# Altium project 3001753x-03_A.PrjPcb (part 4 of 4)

## Sheet 19 - System power rails, GPIO table.SchDoc: System power rails, GPIO table
size A3; PageSetup: Record=PageOptions¦CenterHorizontal=True¦CenterVertical=True¦PrintScale=1.01¦XCorrection=1.00¦YCorrection=1.00¦PrintKind=0¦BorderSize=5000000¦LeftOffset=0¦BottomOffset=0¦Orientation=2¦PaperLength=4200¦PaperWidth=2970¦Scale=100¦PaperSource=15¦PrintQuality=600¦MediaType=1¦DitherType=10¦PrintScaleMode=1¦PaperKind=A3¦PaperIndex=8; Author: Juan Anzola; SheetNumber: 19; SheetTotal: 20
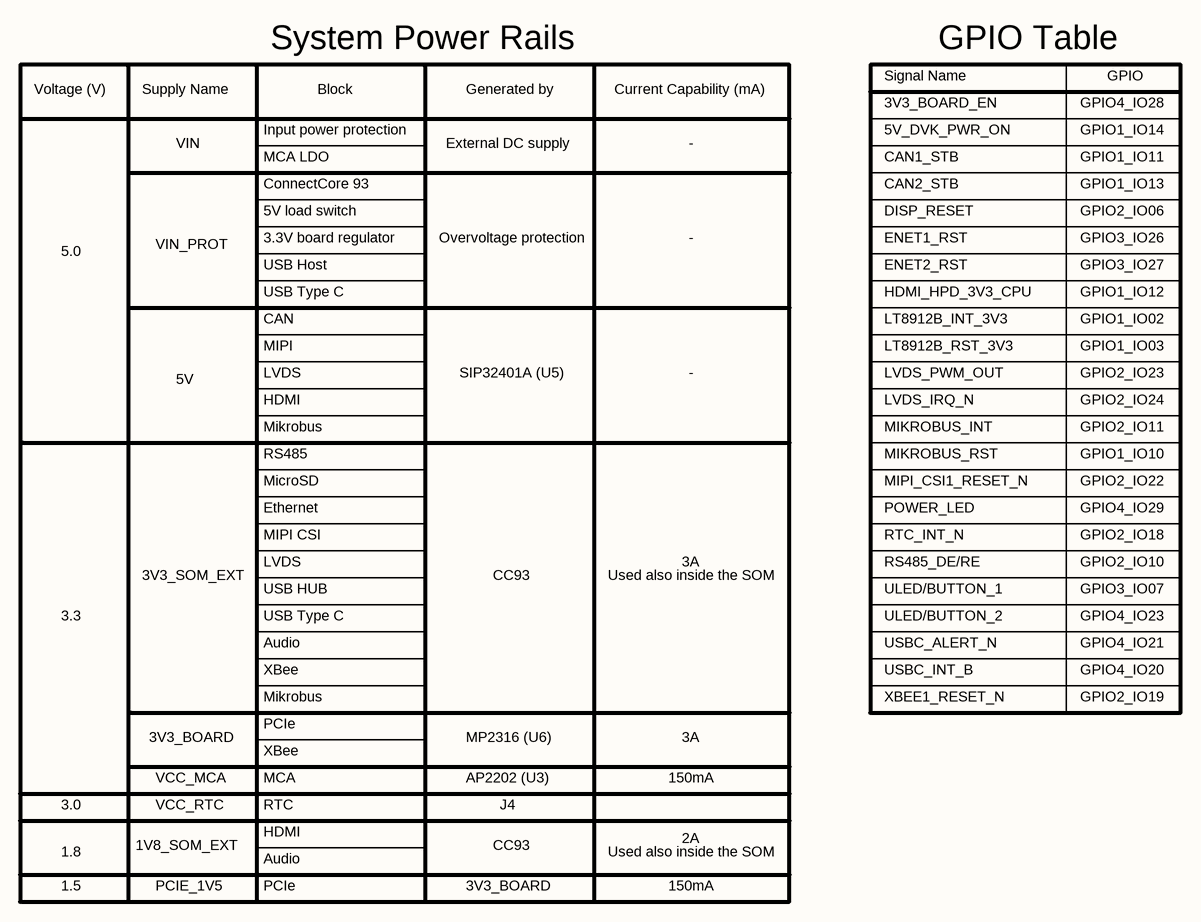
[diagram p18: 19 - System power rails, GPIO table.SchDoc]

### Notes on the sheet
- Voltage (V)
- Supply Name
- System Power Rails
- Block
- Generated by
- Current Capability (mA)
- Signal Name
- GPIO Table
- GPIO
- VIN
- Input power protection
- External DC supply
- -
- 3V3_BOARD_EN
- 5V_DVK_PWR_ON
- GPIO1_IO14
- GPIO4_IO28
- MCA LDO
- ConnectCore 93
- 5V load switch
- CAN1_STB
- CAN2_STB
- DISP_RESET
- GPIO1_IO13
- GPIO1_IO11
- GPIO2_IO06
- 5.0
- VIN_PROT
- USB Host
- 3.3V board regulator
- Overvoltage protection
- ENET1_RST
- ENET2_RST
- GPIO3_IO26
- GPIO3_IO27
- USB Type C
- CAN
- MIPI
- LT8912B_INT_3V3
- HDMI_HPD_3V3_CPU
- LT8912B_RST_3V3
- GPIO1_IO02
- GPIO1_IO03
- GPIO1_IO12
- 5V
- HDMI
- LVDS
- SIP32401A (U5)
- LVDS_PWM_OUT
- LVDS_IRQ_N
- GPIO2_IO24
- GPIO2_IO23
- MicroSD
- Mikrobus
- RS485
- MIPI_CSI1_RESET_N
- MIKROBUS_INT
- MIKROBUS_RST
- GPIO2_IO22
- GPIO2_IO11
- GPIO1_IO10
- Ethernet
- MIPI CSI
- POWER_LED
- RTC_INT_N
- GPIO4_IO29
- GPIO2_IO18
- 3.3
- 3V3_SOM_EXT
- USB HUB
- CC93
- Used also inside the SOM
- 3A
- ULED/BUTTON_1
- RS485_DE/RE
- ULED/BUTTON_2
- GPIO2_IO10
- GPIO3_IO07
- GPIO4_IO23
- Audio
- XBee
- USBC_ALERT_N
- USBC_INT_B
- GPIO4_IO21
- GPIO4_IO20
- 3V3_BOARD
- PCIe
- MP2316 (U6)
- XBEE1_RESET_N
- GPIO2_IO19
- 3.0
- VCC_MCA
- VCC_RTC
- MCA
- RTC
- AP2202 (U3)
- J4
- 150mA
- 1.8
- 1.5
- 1V8_SOM_EXT
- PCIE_1V5
- 2A

## Sheet 20 - History, Mechanicals.SchDoc: History, Mechanicals
size A3; PageSetup: Record=PageOptions¦CenterHorizontal=True¦CenterVertical=True¦PrintScale=1.01¦XCorrection=1.00¦YCorrection=1.00¦PrintKind=0¦BorderSize=5000000¦LeftOffset=0¦BottomOffset=0¦Orientation=2¦PaperLength=4200¦PaperWidth=2970¦Scale=100¦PaperSource=15¦PrintQuality=600¦MediaType=1¦DitherType=10¦PrintScaleMode=1¦PaperKind=A3¦PaperIndex=8; Author: Juan Anzola; SheetNumber: 20; SheetTotal: 20
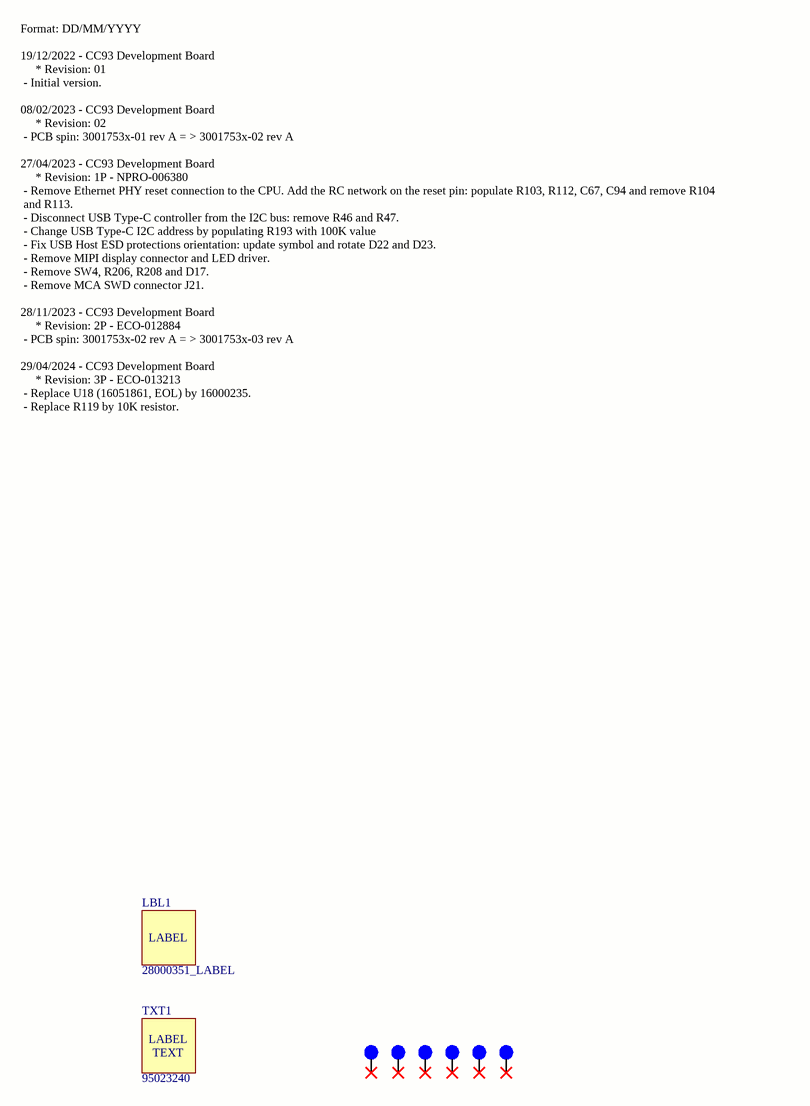
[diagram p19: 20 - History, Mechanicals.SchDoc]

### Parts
FIDUCIAL1  40mil FID  [fiducial_40mil_round]  (value not drawn)  (no BOM)
FIDUCIAL2  40mil FID  [fiducial_40mil_round]  (value not drawn)  (no BOM)
FIDUCIAL3  40mil FID  [fiducial_40mil_round]  (value not drawn)  (no BOM)
FIDUCIAL4  40mil FID  [fiducial_40mil_round]  (value not drawn)  (no BOM)
FIDUCIAL5  40mil FID  [fiducial_40mil_round]  (value not drawn)  (no BOM)
FIDUCIAL6  40mil FID  [fiducial_40mil_round]  (value not drawn)  (no BOM)
LBL1  28000351_LABEL
TXT1  95023240  (mechanical)

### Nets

Not connected (* = marked no-connect by the designer): FIDUCIAL1 1(Fid_1)*; FIDUCIAL2 1(Fid_1)*; FIDUCIAL3 1(Fid_1)*; FIDUCIAL4 1(Fid_1)*; FIDUCIAL5 1(Fid_1)*; FIDUCIAL6 1(Fid_1)*

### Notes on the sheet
- Format: DD/MM/YYYY
  19/12/2022 - CC93 Development Board
  * Revision: 01
  - Initial version.
  08/02/2023 - CC93 Development Board
  * Revision: 02
  - PCB spin: 3001753x-01 rev A = > 3001753x-02 rev A
  27/04/2023 - CC93 Development Board
  * Revision: 1P - NPRO-006380
  - Remove Ethernet PHY reset connection to the CPU. Add the RC network on the reset pin: populate R103, R112, C67, C94 and remove R104
  and R113.
  - Disconnect USB Type-C controller from the I2C bus: remove R46 and R47.
  - Change USB Type-C I2C address by populating R193 with 100K value
  - Fix USB Host ESD protections orientation: update symbol and rotate D22 and D23.
  - Remove MIPI display connector and LED driver.
  - Remove SW4, R206, R208 and D17.
  - Remove MCA SWD connector J21.
  28/11/2023 - CC93 Development Board
  * Revision: 2P - ECO-012884
  - PCB spin: 3001753x-02 rev A = > 3001753x-03 rev A
  29/04/2024 - CC93 Development Board
  * Revision: 3P - ECO-013213
  - Replace U18 (16051861, EOL) by 16000235.
  - Replace R119 by 10K resistor.

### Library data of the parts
FIDUCIAL1-FIDUCIAL6 = CAD0023: 40 Mil Round Fiducial; Part_Type: Mechanical; Component_Life_Cycle_State: Reviewed; Area: 1; Project: SDR Prototype RF Board
LBL1 = 1002170: LBL,Poly White Blank 0.40x0.40; Manufacturer: 3M; Manufacturer_Part_Number: TAAE-014000; Noplace: False; Component_Life_Cycle_State: Created; Area: 100; Project: CCWMX6_SBC board
TXT1 = CAD0111: LBL,.5x.75" 55002179-01 CC93 DVK; Part_Type: Label; Noplace: False; Component_Life_Cycle_State: Pending

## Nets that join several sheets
1V8: 03 - CCIMX93 Power, Control, MCA (6 pins), 18 - Expansion connectors, LEDs and buttons (J47.5 J65.1 R203.1)
1V8_SOM_EXT: 03 - CCIMX93 Power, Control, MCA (J8.1 R44.2), 06 - Shared interfaces lines selection (9 pins), 08 - JTAG, SWD, uSD, Mini PCIe, uSIM (J20.1), 09 - Gigabit Ethernet 1 (R238.1), 10 - Gigabit Ethernet 2 (R239.1), 12 - MIPI to HDMI bridge (35 pins), 16 - Audio (R171.1), 17 - I2C, XBee, MIKROBUS (R172.2 R174.2 U28.2 U28.5)
3V3: 03 - CCIMX93 Power, Control, MCA (8 pins), 07 - Console, CAN, RS485, RTC (J18.3 R73.1), 15 - Bootstrap (C157.2 R151.2 U26.20), 18 - Expansion connectors, LEDs and buttons (J47.3 J65.2)
3V3_BOARD: 02 - Power, reset (7 pins), 08 - JTAG, SWD, uSD, Mini PCIe, uSIM (17 pins), 17 - I2C, XBee, MIKROBUS (L39.1), 18 - Expansion connectors, LEDs and buttons (R15.2)
3V3_RF: 03 - CCIMX93 Power, Control, MCA (U7.F17 U7.F18), 05 - CCIMX93 RF (J12.2), 18 - Expansion connectors, LEDs and buttons (J41.1)
3V3_SOM_EXT: 02 - Power, reset (D35.A R29.2), 03 - CCIMX93 Power, Control, MCA (J7.1 R43.2), 06 - Shared interfaces lines selection (6 pins), 07 - Console, CAN, RS485, RTC (9 pins), 08 - JTAG, SWD, uSD, Mini PCIe, uSIM (R87.2 R88.2), 09 - Gigabit Ethernet 1 (R105.1), 10 - Gigabit Ethernet 2 (J34.1 R205.1), 11 - MIPI switch and display, MIPI camera, LVDS (15 pins), 12 - MIPI to HDMI bridge (D15.A R131.2 R134.2 R137.2), 13 - USB HUB (R141.1), 14 - USB Type C (5 pins), 15 - Bootstrap (R153.2 R155.2 R156.2), 16 - Audio (R160.1 R170.1), 17 - I2C, XBee, MIKROBUS (8 pins), 18 - Expansion connectors, LEDs and buttons (R12.2 R206.2 R207.2)
5V: 02 - Power, reset (R24.2), 07 - Console, CAN, RS485, RTC (6 pins), 11 - MIPI switch and display, MIPI camera, LVDS (L17.1 R216.1), 12 - MIPI to HDMI bridge (C111.2 C112.2 U18.1), 17 - I2C, XBee, MIKROBUS (C146.1 J40.7), 18 - Expansion connectors, LEDs and buttons (R195.2)
GND: 02 - Power, reset (49 pins), 03 - CCIMX93 Power, Control, MCA (166 pins), 05 - CCIMX93 RF (11 pins), 06 - Shared interfaces lines selection (9 pins), 07 - Console, CAN, RS485, RTC (49 pins), 08 - JTAG, SWD, uSD, Mini PCIe, uSIM (69 pins), 09 - Gigabit Ethernet 1 (36 pins), 10 - Gigabit Ethernet 2 (35 pins), 11 - MIPI switch and display, MIPI camera, LVDS (46 pins), 12 - MIPI to HDMI bridge (56 pins), 13 - USB HUB (36 pins), 14 - USB Type C (23 pins), 15 - Bootstrap (8 pins), 16 - Audio (29 pins), 17 - I2C, XBee, MIKROBUS (10 pins), 18 - Expansion connectors, LEDs and buttons (17 pins)
LDO2: 03 - CCIMX93 Power, Control, MCA (R36.1), 18 - Expansion connectors, LEDs and buttons (J47.1)
LDO3: 03 - CCIMX93 Power, Control, MCA (R37.1), 08 - JTAG, SWD, uSD, Mini PCIe, uSIM (R243.1), 18 - Expansion connectors, LEDs and buttons (J47.2)
MUX_3V3_1V8: 03 - CCIMX93 Power, Control, MCA (R38.1 R39.1), 08 - JTAG, SWD, uSD, Mini PCIe, uSIM (R84.2 R85.2)
SHLD: 09 - Gigabit Ethernet 1 (J26.SHLD1 J26.SHLD2 R100.2), 10 - Gigabit Ethernet 2 (J27.SHLD1 J27.SHLD2), 12 - MIPI to HDMI bridge (J32.M1 J32.M2 J32.M3 J32.M4), 13 - USB HUB (J33.SH1 J33.SH2 J33.SH3 J33.SH4), 14 - USB Type C (J63.MT1 J63.MT2 J63.MT3 J63.MT4)
SUPERCAP: 02 - Power, reset (C9.1 J5.2 R242.1), 07 - Console, CAN, RS485, RTC (R227.2)
SWIN: 03 - CCIMX93 Power, Control, MCA (R41.1), 18 - Expansion connectors, LEDs and buttons (J47.7)
SWOUT: 03 - CCIMX93 Power, Control, MCA (R42.1), 18 - Expansion connectors, LEDs and buttons (J47.8)
VCC_MCA: 02 - Power, reset (7 pins), 03 - CCIMX93 Power, Control, MCA (J9.1 U7.AM21), 08 - JTAG, SWD, uSD, Mini PCIe, uSIM (J21.1 SWD.1 SWD.5), 18 - Expansion connectors, LEDs and buttons (J42.1 J42.2 J47.6)
VCC_RTC: 02 - Power, reset (D2.2 R17.2), 07 - Console, CAN, RS485, RTC (R226.2)
VIN_PROT: 02 - Power, reset (15 pins), 03 - CCIMX93 Power, Control, MCA (J6.1 R33.1), 04 - CCIMX93 Digital interfaces (U7.B6 U7.E7), 13 - USB HUB (C139.1 U19.7), 14 - USB Type C (6 pins), 17 - I2C, XBee, MIKROBUS (R196.1), 18 - Expansion connectors, LEDs and buttons (R154.2)
3V3_BOARD_EN: 02 - Power, reset (Q11.G), 04 - CCIMX93 Digital interfaces (U7.AG25)
5V_DVK_PWR_ON: 02 - Power, reset (R29.1 U5.4), 04 - CCIMX93 Digital interfaces (U7.D18)
15.4_SPI_CLK: 05 - CCIMX93 RF (U7.F8), 18 - Expansion connectors, LEDs and buttons (J44.10)
15.4_SPI_FRM: 05 - CCIMX93 RF (U7.F4), 18 - Expansion connectors, LEDs and buttons (J44.2)
15.4_SPI_INT: 05 - CCIMX93 RF (U7.F5), 18 - Expansion connectors, LEDs and buttons (J44.4)
15.4_SPI_RXD: 05 - CCIMX93 RF (U7.F6), 18 - Expansion connectors, LEDs and buttons (J44.6)
15.4_SPI_TXD: 05 - CCIMX93 RF (U7.F7), 18 - Expansion connectors, LEDs and buttons (J44.8)
ADC_IN0: 04 - CCIMX93 Digital interfaces (U7.K29), 18 - Expansion connectors, LEDs and buttons (J48.1)
ADC_IN1: 04 - CCIMX93 Digital interfaces (U7.L29), 18 - Expansion connectors, LEDs and buttons (J48.3)
ADC_IN2: 04 - CCIMX93 Digital interfaces (U7.AG27), 18 - Expansion connectors, LEDs and buttons (J48.5)
ADC_IN3: 04 - CCIMX93 Digital interfaces (U7.AG26), 18 - Expansion connectors, LEDs and buttons (J48.7)
AUD_I2C_SCL: 16 - Audio (U27.51), 17 - I2C, XBee, MIKROBUS (R179.2)
AUD_I2C_SDA: 16 - Audio (U27.52), 17 - I2C, XBee, MIKROBUS (R183.2)
BT_DEV_WAKE: 05 - CCIMX93 RF (U7.G12), 18 - Expansion connectors, LEDs and buttons (J41.15)
BT_HOST_WAKE: 05 - CCIMX93 RF (U7.G17), 18 - Expansion connectors, LEDs and buttons (J41.13)
BT_UART1_CTS: 05 - CCIMX93 RF (R63.2), 18 - Expansion connectors, LEDs and buttons (J41.7)
BT_UART1_RTS: 05 - CCIMX93 RF (R64.2), 15 - Bootstrap (SW3.2 U26.3)
BT_UART1_RTS_PROT: 15 - Bootstrap (U26.17), 18 - Expansion connectors, LEDs and buttons (J41.9)
BT_UART1_RX: 05 - CCIMX93 RF (R62.2), 18 - Expansion connectors, LEDs and buttons (J41.5)
BT_UART1_TX: 05 - CCIMX93 RF (R61.2), 15 - Bootstrap (R159.2 SW3.1 U26.2)
BT_UART1_TX_PROT: 15 - Bootstrap (U26.18), 18 - Expansion connectors, LEDs and buttons (J41.3)
CAN1_RX: 04 - CCIMX93 Digital interfaces (U7.U29), 07 - Console, CAN, RS485, RTC (U8.4)
CAN1_STB: 04 - CCIMX93 Digital interfaces (U7.C17), 15 - Bootstrap (R158.2 SW3.3 U26.4)
CAN1_STB_PROT: 07 - Console, CAN, RS485, RTC (R67.2 U8.8), 15 - Bootstrap (U26.16)
CAN1_TX: 04 - CCIMX93 Digital interfaces (U7.T29), 07 - Console, CAN, RS485, RTC (U8.1)
CAN2_RX: 04 - CCIMX93 Digital interfaces (U7.R29), 07 - Console, CAN, RS485, RTC (U10.4)
CAN2_STB: 04 - CCIMX93 Digital interfaces (U7.E17), 15 - Bootstrap (R157.2 SW3.4 U26.5)
CAN2_STB_PROT: 07 - Console, CAN, RS485, RTC (R78.2 U10.8), 15 - Bootstrap (U26.15)
CAN2_TX: 04 - CCIMX93 Digital interfaces (U7.P29), 07 - Console, CAN, RS485, RTC (U10.1)
CLKIN1: 03 - CCIMX93 Power, Control, MCA (U7.AM10), 18 - Expansion connectors, LEDs and buttons (J48.2)
CLKIN2: 03 - CCIMX93 Power, Control, MCA (U7.AM11), 18 - Expansion connectors, LEDs and buttons (J48.4)
CONSOLE_RX: 04 - CCIMX93 Digital interfaces (U7.V29), 07 - Console, CAN, RS485, RTC (D9.2 J18.2 R68.1)
CONSOLE_TX: 04 - CCIMX93 Digital interfaces (U7.W29), 07 - Console, CAN, RS485, RTC (D10.2 J18.1 R69.1)
DISP_RESET: 04 - CCIMX93 Digital interfaces (U7.AA1), 11 - MIPI switch and display, MIPI camera, LVDS (J29.7 R214.2 R218.1)
ENET1_MDC: 04 - CCIMX93 Digital interfaces (U7.A10), 09 - Gigabit Ethernet 1 (U13.7)
ENET1_MDIO: 04 - CCIMX93 Digital interfaces (U7.A11), 09 - Gigabit Ethernet 1 (R99.2 U13.8)
ENET1_RD0: 04 - CCIMX93 Digital interfaces (U7.A16), 09 - Gigabit Ethernet 1 (U13.44)
ENET1_RD1: 04 - CCIMX93 Digital interfaces (U7.A15), 09 - Gigabit Ethernet 1 (U13.45)
ENET1_RD2: 04 - CCIMX93 Digital interfaces (U7.A14), 09 - Gigabit Ethernet 1 (U13.47)
ENET1_RD3: 04 - CCIMX93 Digital interfaces (U7.A13), 09 - Gigabit Ethernet 1 (U13.48)
ENET1_RX_CTL: 04 - CCIMX93 Digital interfaces (U7.A17), 09 - Gigabit Ethernet 1 (U13.43)
ENET1_RXC: 04 - CCIMX93 Digital interfaces (U7.A18), 09 - Gigabit Ethernet 1 (U13.46)
ENET1_TD0: 04 - CCIMX93 Digital interfaces (U7.A22), 09 - Gigabit Ethernet 1 (U13.50)
ENET1_TD1: 04 - CCIMX93 Digital interfaces (U7.A21), 09 - Gigabit Ethernet 1 (U13.51)
ENET1_TD2: 04 - CCIMX93 Digital interfaces (U7.A20), 09 - Gigabit Ethernet 1 (U13.54)
ENET1_TD3: 04 - CCIMX93 Digital interfaces (U7.A19), 09 - Gigabit Ethernet 1 (U13.55)
ENET1_TX_CTL: 04 - CCIMX93 Digital interfaces (U7.A23), 09 - Gigabit Ethernet 1 (U13.56)
ENET1_TXC: 04 - CCIMX93 Digital interfaces (U7.A24), 09 - Gigabit Ethernet 1 (U13.53)
ENET2_MDC: 04 - CCIMX93 Digital interfaces (U7.AF1), 10 - Gigabit Ethernet 2 (U14.7)
ENET2_MDIO: 04 - CCIMX93 Digital interfaces (U7.AG1), 10 - Gigabit Ethernet 2 (R109.2 U14.8)
ENET2_RD0: 06 - Shared interfaces lines selection (J54.1), 10 - Gigabit Ethernet 2 (U14.44)
ENET2_RD0/UART4_RX: 04 - CCIMX93 Digital interfaces (U7.D21), 06 - Shared interfaces lines selection (J54.2)
ENET2_RD1: 06 - Shared interfaces lines selection (J56.1), 10 - Gigabit Ethernet 2 (U14.45)
ENET2_RD1/GPIO4_IO25: 04 - CCIMX93 Digital interfaces (U7.D23), 06 - Shared interfaces lines selection (J56.2)
ENET2_RD2: 06 - Shared interfaces lines selection (J58.1), 10 - Gigabit Ethernet 2 (U14.47)
ENET2_RD2/UART4_CTS: 04 - CCIMX93 Digital interfaces (U7.C20), 06 - Shared interfaces lines selection (J58.2)
ENET2_RD3: 06 - Shared interfaces lines selection (J60.1), 10 - Gigabit Ethernet 2 (U14.48)
ENET2_RD3/GPIO4_IO27: 04 - CCIMX93 Digital interfaces (U7.B22), 06 - Shared interfaces lines selection (J60.2)
ENET2_RX_CTL: 06 - Shared interfaces lines selection (J55.1), 10 - Gigabit Ethernet 2 (U14.43)
ENET2_RX_CTL/GPIO4_IO22: 04 - CCIMX93 Digital interfaces (U7.C23), 06 - Shared interfaces lines selection (J55.2)
ENET2_RXC: 06 - Shared interfaces lines selection (J53.1), 10 - Gigabit Ethernet 2 (U14.46)
ENET2_RXC/GPIO4_IO23: 04 - CCIMX93 Digital interfaces (U7.D22), 06 - Shared interfaces lines selection (J53.2)
ENET2_TD0: 06 - Shared interfaces lines selection (J57.1), 10 - Gigabit Ethernet 2 (U14.50)
ENET2_TD0/UART4_TX: 04 - CCIMX93 Digital interfaces (U7.C22), 06 - Shared interfaces lines selection (J57.2)
ENET2_TD1: 06 - Shared interfaces lines selection (J59.1), 10 - Gigabit Ethernet 2 (U14.51)
ENET2_TD1/UART4_RTS: 04 - CCIMX93 Digital interfaces (U7.D20), 06 - Shared interfaces lines selection (J59.2)
ENET2_TD2: 06 - Shared interfaces lines selection (J45.1), 10 - Gigabit Ethernet 2 (U14.54)
ENET2_TD2/GPIO4_IO17: 04 - CCIMX93 Digital interfaces (U7.C21), 06 - Shared interfaces lines selection (J45.2)
ENET2_TD3: 06 - Shared interfaces lines selection (J52.1), 10 - Gigabit Ethernet 2 (U14.55)
ENET2_TD3/GPIO4_IO16: 04 - CCIMX93 Digital interfaces (U7.B21), 06 - Shared interfaces lines selection (J52.2)
ENET2_TX_CTL: 06 - Shared interfaces lines selection (J51.1), 10 - Gigabit Ethernet 2 (U14.56)
ENET2_TX_CTL/GPIO4_IO20: 04 - CCIMX93 Digital interfaces (U7.B19), 06 - Shared interfaces lines selection (J51.2)
ENET2_TXC: 06 - Shared interfaces lines selection (J43.1), 10 - Gigabit Ethernet 2 (U14.53)
ENET2_TXC/GPIO4_IO21: 04 - CCIMX93 Digital interfaces (U7.B20), 06 - Shared interfaces lines selection (J43.2)
GPIO3_IO26_1V8: 04 - CCIMX93 Digital interfaces (U7.AL18), 12 - MIPI to HDMI bridge (R244.2), 18 - Expansion connectors, LEDs and buttons (J65.3)
GPIO3_IO27_1V8: 04 - CCIMX93 Digital interfaces (U7.D25), 18 - Expansion connectors, LEDs and buttons (J65.5)
GPIO4_IO16_1V8: 06 - Shared interfaces lines selection (J52.3), 18 - Expansion connectors, LEDs and buttons (J65.7)
GPIO4_IO17_1V8: 06 - Shared interfaces lines selection (J45.3), 18 - Expansion connectors, LEDs and buttons (J65.9)
GPIO4_IO22_1V8: 06 - Shared interfaces lines selection (J55.3), 18 - Expansion connectors, LEDs and buttons (J65.4)
GPIO4_IO25_1V8: 06 - Shared interfaces lines selection (J56.3), 18 - Expansion connectors, LEDs and buttons (J65.6)
GPIO4_IO27_1V8: 06 - Shared interfaces lines selection (J60.3), 18 - Expansion connectors, LEDs and buttons (J65.8)
HDMI_HPD_3V3_CPU: 04 - CCIMX93 Digital interfaces (U7.C18), 12 - MIPI to HDMI bridge (Q3.D R131.1 R132.2)
HDMI_SCL_1V8: 12 - MIPI to HDMI bridge (U18.17), 17 - I2C, XBee, MIKROBUS (R185.2)
HDMI_SDA_1V8: 12 - MIPI to HDMI bridge (U18.18), 17 - I2C, XBee, MIKROBUS (R187.2)
I2C3_SCL: 04 - CCIMX93 Digital interfaces (U7.AK25), 17 - I2C, XBee, MIKROBUS (7 pins)
I2C3_SDA: 04 - CCIMX93 Digital interfaces (U7.AK24), 17 - I2C, XBee, MIKROBUS (7 pins)
I2C4_SCL: 04 - CCIMX93 Digital interfaces (U7.F28), 17 - I2C, XBee, MIKROBUS (R173.1 R176.2 U28.6)
I2C4_SDA: 04 - CCIMX93 Digital interfaces (U7.E29), 17 - I2C, XBee, MIKROBUS (R175.1 R177.2 U28.3)
I3C2_SCL: 04 - CCIMX93 Digital interfaces (R104.1), 18 - Expansion connectors, LEDs and buttons (J66.1)
I3C2_SDA: 04 - CCIMX93 Digital interfaces (R241.1), 18 - Expansion connectors, LEDs and buttons (J66.2)
IMX9_ON_OFF: 02 - Power, reset (R4.2), 03 - CCIMX93 Power, Control, MCA (U7.AG18)
JTAG_TCK: 03 - CCIMX93 Power, Control, MCA (U7.AG20), 08 - JTAG, SWD, uSD, Mini PCIe, uSIM (J20.4)
JTAG_TDI: 03 - CCIMX93 Power, Control, MCA (U7.AH27), 08 - JTAG, SWD, uSD, Mini PCIe, uSIM (J20.8)
JTAG_TDO: 03 - CCIMX93 Power, Control, MCA (U7.AG21), 08 - JTAG, SWD, uSD, Mini PCIe, uSIM (J20.6)
JTAG_TMS: 03 - CCIMX93 Power, Control, MCA (U7.AH28), 08 - JTAG, SWD, uSD, Mini PCIe, uSIM (J20.2)
LINE1_IN_L: 16 - Audio (L35.1), 18 - Expansion connectors, LEDs and buttons (J46.2)
LINE1_IN_R: 16 - Audio (L34.1), 18 - Expansion connectors, LEDs and buttons (J46.1)
LINE2_IN_L: 16 - Audio (L37.1), 18 - Expansion connectors, LEDs and buttons (J46.4)
LINE2_IN_R: 16 - Audio (L36.1), 18 - Expansion connectors, LEDs and buttons (J46.3)
LINE_OUT_L: 16 - Audio (U27.24), 18 - Expansion connectors, LEDs and buttons (J46.6)
LINE_OUT_R: 16 - Audio (U27.23), 18 - Expansion connectors, LEDs and buttons (J46.5)
LT8912B_CLK_N: 11 - MIPI switch and display, MIPI camera, LVDS (U15.16), 12 - MIPI to HDMI bridge (U17.8)
LT8912B_CLK_P: 11 - MIPI switch and display, MIPI camera, LVDS (U15.17), 12 - MIPI to HDMI bridge (U17.7)
LT8912B_D0_N: 11 - MIPI switch and display, MIPI camera, LVDS (U16.14), 12 - MIPI to HDMI bridge (U17.2)
LT8912B_D0_P: 11 - MIPI switch and display, MIPI camera, LVDS (U16.15), 12 - MIPI to HDMI bridge (U17.1)
LT8912B_D1_N: 11 - MIPI switch and display, MIPI camera, LVDS (U16.12), 12 - MIPI to HDMI bridge (U17.4)
LT8912B_D1_P: 11 - MIPI switch and display, MIPI camera, LVDS (U16.13), 12 - MIPI to HDMI bridge (U17.3)
LT8912B_D2_N: 11 - MIPI switch and display, MIPI camera, LVDS (U15.14), 12 - MIPI to HDMI bridge (U17.10)
LT8912B_D2_P: 11 - MIPI switch and display, MIPI camera, LVDS (U15.15), 12 - MIPI to HDMI bridge (U17.9)
LT8912B_D3_N: 11 - MIPI switch and display, MIPI camera, LVDS (U15.12), 12 - MIPI to HDMI bridge (U17.12)
LT8912B_D3_P: 11 - MIPI switch and display, MIPI camera, LVDS (U15.13), 12 - MIPI to HDMI bridge (U17.11)
LT8912B_INT_3V3: 04 - CCIMX93 Digital interfaces (U7.V1), 12 - MIPI to HDMI bridge (Q4.D R134.1 R135.2)
LT8912B_RST_3V3: 04 - CCIMX93 Digital interfaces (U7.W1), 12 - MIPI to HDMI bridge (Q5.D R137.1 R138.2)
LT8912B_SCL: 12 - MIPI to HDMI bridge (U17.62), 17 - I2C, XBee, MIKROBUS (R189.2)
LT8912B_SDA: 12 - MIPI to HDMI bridge (U17.61), 17 - I2C, XBee, MIKROBUS (R191.2)
LVDS_CLK_N: 04 - CCIMX93 Digital interfaces (U7.AJ19), 11 - MIPI switch and display, MIPI camera, LVDS (L15.1)
LVDS_CLK_P: 04 - CCIMX93 Digital interfaces (U7.AJ18), 11 - MIPI switch and display, MIPI camera, LVDS (L15.4)
LVDS_D0_N: 04 - CCIMX93 Digital interfaces (U7.AJ15), 11 - MIPI switch and display, MIPI camera, LVDS (L12.1)
LVDS_D0_P: 04 - CCIMX93 Digital interfaces (U7.AJ16), 11 - MIPI switch and display, MIPI camera, LVDS (L12.4)
LVDS_D1_N: 04 - CCIMX93 Digital interfaces (U7.AK15), 11 - MIPI switch and display, MIPI camera, LVDS (L13.1)
LVDS_D1_P: 04 - CCIMX93 Digital interfaces (U7.AK16), 11 - MIPI switch and display, MIPI camera, LVDS (L13.4)
LVDS_D2_N: 04 - CCIMX93 Digital interfaces (U7.AH16), 11 - MIPI switch and display, MIPI camera, LVDS (L14.1)
LVDS_D2_P: 04 - CCIMX93 Digital interfaces (U7.AH15), 11 - MIPI switch and display, MIPI camera, LVDS (L14.4)
LVDS_D3_N: 04 - CCIMX93 Digital interfaces (U7.AK19), 11 - MIPI switch and display, MIPI camera, LVDS (L16.1)
LVDS_D3_P: 04 - CCIMX93 Digital interfaces (U7.AK18), 11 - MIPI switch and display, MIPI camera, LVDS (L16.4)
LVDS_I2C_SCL: 11 - MIPI switch and display, MIPI camera, LVDS (J31.17), 17 - I2C, XBee, MIKROBUS (R178.2)
LVDS_I2C_SDA: 11 - MIPI switch and display, MIPI camera, LVDS (J31.18), 17 - I2C, XBee, MIKROBUS (R182.2)
LVDS_IRQ_N: 04 - CCIMX93 Digital interfaces (U7.C24), 11 - MIPI switch and display, MIPI camera, LVDS (J31.19 R118.2)
LVDS_PWM_OUT: 04 - CCIMX93 Digital interfaces (U7.E27), 11 - MIPI switch and display, MIPI camera, LVDS (J31.16)
MCA_CLKOUT32K: 03 - CCIMX93 Power, Control, MCA (U7.AL21), 18 - Expansion connectors, LEDs and buttons (J42.3)
MCA_IO9: 03 - CCIMX93 Power, Control, MCA (U7.AG29), 18 - Expansion connectors, LEDs and buttons (J42.13)
MCA_IO10: 03 - CCIMX93 Power, Control, MCA (U7.AF29), 18 - Expansion connectors, LEDs and buttons (J42.15)
MCA_IO11: 03 - CCIMX93 Power, Control, MCA (U7.AM26), 18 - Expansion connectors, LEDs and buttons (J42.17)
MCA_IO12: 03 - CCIMX93 Power, Control, MCA (U7.AM25), 18 - Expansion connectors, LEDs and buttons (J42.4)
MCA_IO13: 03 - CCIMX93 Power, Control, MCA (U7.AL22), 18 - Expansion connectors, LEDs and buttons (J42.6)
MCA_IO14: 03 - CCIMX93 Power, Control, MCA (U7.AL26), 18 - Expansion connectors, LEDs and buttons (J42.8)
MCA_IO15: 03 - CCIMX93 Power, Control, MCA (U7.AL25), 18 - Expansion connectors, LEDs and buttons (J42.10)
MCA_IO16: 03 - CCIMX93 Power, Control, MCA (U7.AL24), 18 - Expansion connectors, LEDs and buttons (J42.12)
MCA_IO17: 03 - CCIMX93 Power, Control, MCA (U7.AL23), 18 - Expansion connectors, LEDs and buttons (J42.14)
MCA_IO18: 03 - CCIMX93 Power, Control, MCA (U7.AM23), 18 - Expansion connectors, LEDs and buttons (J42.16)
MCA_UART_CTS: 03 - CCIMX93 Power, Control, MCA (U7.AN23), 18 - Expansion connectors, LEDs and buttons (J42.9)
MCA_UART_RTS: 03 - CCIMX93 Power, Control, MCA (U7.AL27), 18 - Expansion connectors, LEDs and buttons (J42.11)
MCA_UART_RX: 03 - CCIMX93 Power, Control, MCA (U7.AN22), 18 - Expansion connectors, LEDs and buttons (J42.7)
MCA_UART_TX: 03 - CCIMX93 Power, Control, MCA (U7.AN21), 18 - Expansion connectors, LEDs and buttons (J42.5)
MCA_VIN_DET: 02 - Power, reset (R22.2 U4.1), 03 - CCIMX93 Power, Control, MCA (U7.AM27)
MCA_VREF_OUT: 03 - CCIMX93 Power, Control, MCA (U7.AM24), 18 - Expansion connectors, LEDs and buttons (J42.18)
MIKROBUS_ADC: 17 - I2C, XBee, MIKROBUS (J39.1), 18 - Expansion connectors, LEDs and buttons (J48.9)
MIKROBUS_INT: 04 - CCIMX93 Digital interfaces (U7.N29), 17 - I2C, XBee, MIKROBUS (J40.2 R50.1)
MIKROBUS_PWM: 17 - I2C, XBee, MIKROBUS (J40.1), 18 - Expansion connectors, LEDs and buttons (J48.10)
MIKROBUS_RST: 04 - CCIMX93 Digital interfaces (U7.Y1), 17 - I2C, XBee, MIKROBUS (J39.2)
MIKROBUS_UART_RX: 06 - Shared interfaces lines selection (J62.3), 17 - I2C, XBee, MIKROBUS (J40.4)
MIKROBUS_UART_TX: 06 - Shared interfaces lines selection (J61.3), 17 - I2C, XBee, MIKROBUS (J40.3)
MIPI_CSI1_CLK_N: 04 - CCIMX93 Digital interfaces (U7.AM14), 11 - MIPI switch and display, MIPI camera, LVDS (J30.8)
MIPI_CSI1_CLK_P: 04 - CCIMX93 Digital interfaces (U7.AM13), 11 - MIPI switch and display, MIPI camera, LVDS (J30.7)
MIPI_CSI1_DATA0_N: 04 - CCIMX93 Digital interfaces (U7.AL16), 11 - MIPI switch and display, MIPI camera, LVDS (J30.14)
MIPI_CSI1_DATA0_P: 04 - CCIMX93 Digital interfaces (U7.AL15), 11 - MIPI switch and display, MIPI camera, LVDS (J30.13)
MIPI_CSI1_DATA1_N: 04 - CCIMX93 Digital interfaces (U7.AL13), 11 - MIPI switch and display, MIPI camera, LVDS (J30.11)
MIPI_CSI1_DATA1_P: 04 - CCIMX93 Digital interfaces (U7.AL12), 11 - MIPI switch and display, MIPI camera, LVDS (J30.10)
MIPI_CSI1_I2C_SCL: 11 - MIPI switch and display, MIPI camera, LVDS (J30.3), 17 - I2C, XBee, MIKROBUS (R184.2)
MIPI_CSI1_I2C_SDA: 11 - MIPI switch and display, MIPI camera, LVDS (J30.2), 17 - I2C, XBee, MIKROBUS (R186.2)
MIPI_CSI1_RESET_N: 04 - CCIMX93 Digital interfaces (U7.E28), 11 - MIPI switch and display, MIPI camera, LVDS (J30.5)
MIPI_DSI1_CLK_N: 04 - CCIMX93 Digital interfaces (U7.AN6), 11 - MIPI switch and display, MIPI camera, LVDS (U15.2)
MIPI_DSI1_CLK_P: 04 - CCIMX93 Digital interfaces (U7.AN7), 11 - MIPI switch and display, MIPI camera, LVDS (U15.1)
MIPI_DSI1_DATA0_N: 04 - CCIMX93 Digital interfaces (U7.AN9), 11 - MIPI switch and display, MIPI camera, LVDS (U16.4)
MIPI_DSI1_DATA0_P: 04 - CCIMX93 Digital interfaces (U7.AN10), 11 - MIPI switch and display, MIPI camera, LVDS (U16.3)
MIPI_DSI1_DATA1_N: 04 - CCIMX93 Digital interfaces (U7.AN12), 11 - MIPI switch and display, MIPI camera, LVDS (U16.6)
MIPI_DSI1_DATA1_P: 04 - CCIMX93 Digital interfaces (U7.AN13), 11 - MIPI switch and display, MIPI camera, LVDS (U16.5)
MIPI_DSI1_DATA2_N: 04 - CCIMX93 Digital interfaces (U7.AN15), 11 - MIPI switch and display, MIPI camera, LVDS (U15.4)
MIPI_DSI1_DATA2_P: 04 - CCIMX93 Digital interfaces (U7.AN16), 11 - MIPI switch and display, MIPI camera, LVDS (U15.3)
MIPI_DSI1_DATA3_N: 04 - CCIMX93 Digital interfaces (U7.AN18), 11 - MIPI switch and display, MIPI camera, LVDS (U15.6)
MIPI_DSI1_DATA3_P: 04 - CCIMX93 Digital interfaces (U7.AN19), 11 - MIPI switch and display, MIPI camera, LVDS (U15.5)
PCIE_I2C_SCL: 08 - JTAG, SWD, uSD, Mini PCIe, uSIM (J19.30), 17 - I2C, XBee, MIKROBUS (R188.2)
PCIE_I2C_SDA: 08 - JTAG, SWD, uSD, Mini PCIe, uSIM (J19.32), 17 - I2C, XBee, MIKROBUS (R190.2)
PCM_CLK: 05 - CCIMX93 RF (U7.G13), 16 - Audio (R161.1), 18 - Expansion connectors, LEDs and buttons (J44.3)
PCM_IN: 05 - CCIMX93 RF (U7.G14), 16 - Audio (R164.1), 18 - Expansion connectors, LEDs and buttons (J44.5)
PCM_MCLK: 05 - CCIMX93 RF (U7.A26), 18 - Expansion connectors, LEDs and buttons (J44.1)
PCM_OUT: 05 - CCIMX93 RF (U7.F13), 16 - Audio (R163.1), 18 - Expansion connectors, LEDs and buttons (J44.7)
PCM_SYNC: 05 - CCIMX93 RF (U7.F14), 16 - Audio (R162.1), 18 - Expansion connectors, LEDs and buttons (J44.9)
POR_B: 02 - Power, reset (R6.2), 03 - CCIMX93 Power, Control, MCA (U7.AH10), 08 - JTAG, SWD, uSD, Mini PCIe, uSIM (J20.10), 15 - Bootstrap (R152.1)
POWER_LED: 04 - CCIMX93 Digital interfaces (U7.AG28), 18 - Expansion connectors, LEDs and buttons (Q2.G R203.2 R204.1)
PWR_ON: 02 - Power, reset (R13.1), 03 - CCIMX93 Power, Control, MCA (U7.AJ12)
RS485_DE/RE: 04 - CCIMX93 Digital interfaces (U7.M29), 07 - Console, CAN, RS485, RTC (R234.1)
RS485_RX: 06 - Shared interfaces lines selection (J62.1), 07 - Console, CAN, RS485, RTC (R233.1)
RS485_TX: 06 - Shared interfaces lines selection (J61.1), 07 - Console, CAN, RS485, RTC (R235.1)
RTC_I2C_SCL: 07 - Console, CAN, RS485, RTC (U30.3), 17 - I2C, XBee, MIKROBUS (R230.2)
RTC_I2C_SDA: 07 - Console, CAN, RS485, RTC (U30.4), 17 - I2C, XBee, MIKROBUS (R231.2)
RTC_INT_N: 04 - CCIMX93 Digital interfaces (U7.AN4), 07 - Console, CAN, RS485, RTC (R228.1)
SAI3_MCLK: 04 - CCIMX93 Digital interfaces (U7.B24), 16 - Audio (TP13.1 U27.5)
SAI3_RXD: 04 - CCIMX93 Digital interfaces (U7.E21), 16 - Audio (TP17.1 U27.7)
SAI3_TXC: 04 - CCIMX93 Digital interfaces (U7.E23), 16 - Audio (TP14.1 U27.8)
SAI3_TXD: 04 - CCIMX93 Digital interfaces (U7.E20), 16 - Audio (TP16.1 U27.9)
SAI3_TXFS: 04 - CCIMX93 Digital interfaces (U7.C19), 16 - Audio (TP15.1 U27.10)
SD2_CD_B: 04 - CCIMX93 Digital interfaces (R113.1), 08 - JTAG, SWD, uSD, Mini PCIe, uSIM (D24.1 J23.9 J23.10 R91.2)
SD2_CLK: 04 - CCIMX93 Digital interfaces (R240.1), 08 - JTAG, SWD, uSD, Mini PCIe, uSIM (D30.1 R93.1)
SD2_CMD: 04 - CCIMX93 Digital interfaces (U7.F1), 08 - JTAG, SWD, uSD, Mini PCIe, uSIM (D28.1 J23.3 R90.1)
SD2_DATA0: 04 - CCIMX93 Digital interfaces (U7.G1), 08 - JTAG, SWD, uSD, Mini PCIe, uSIM (D25.1 J23.7 R92.1)
SD2_DATA1: 04 - CCIMX93 Digital interfaces (U7.H1), 08 - JTAG, SWD, uSD, Mini PCIe, uSIM (D27.1 J23.8)
SD2_DATA2: 04 - CCIMX93 Digital interfaces (U7.J1), 08 - JTAG, SWD, uSD, Mini PCIe, uSIM (D29.1 J23.1)
SD2_DATA3: 04 - CCIMX93 Digital interfaces (U7.K1), 08 - JTAG, SWD, uSD, Mini PCIe, uSIM (D26.1 J23.2)
SD2_VSELECT: 03 - CCIMX93 Power, Control, MCA (U7.AH13), 04 - CCIMX93 Digital interfaces (U7.AN5)
SPI8_MISO: 04 - CCIMX93 Digital interfaces (U7.E22), 17 - I2C, XBee, MIKROBUS (J39.5)
SPI8_MOSI: 04 - CCIMX93 Digital interfaces (U7.E18), 17 - I2C, XBee, MIKROBUS (J39.6)
SPI8_SCK: 04 - CCIMX93 Digital interfaces (U7.D17), 17 - I2C, XBee, MIKROBUS (J39.4)
SPI8_SS: 04 - CCIMX93 Digital interfaces (U7.E19), 17 - I2C, XBee, MIKROBUS (J39.3)
SPKL_N: 16 - Audio (U27.22), 18 - Expansion connectors, LEDs and buttons (J46.8)
SPKL_P: 16 - Audio (U27.20), 18 - Expansion connectors, LEDs and buttons (J46.7)
SPKR_N: 16 - Audio (U27.15), 18 - Expansion connectors, LEDs and buttons (J46.10)
SPKR_P: 16 - Audio (U27.17), 18 - Expansion connectors, LEDs and buttons (J46.9)
SW_EN: 03 - CCIMX93 Power, Control, MCA (U7.F2), 18 - Expansion connectors, LEDs and buttons (J47.9)
SWD_CLK/PWR_IO: 02 - Power, reset (R1.1 R2.2), 03 - CCIMX93 Power, Control, MCA (U7.AN24), 08 - JTAG, SWD, uSD, Mini PCIe, uSIM (J21.4 SWD.4)
SWD_DIO: 03 - CCIMX93 Power, Control, MCA (U7.AN26), 08 - JTAG, SWD, uSD, Mini PCIe, uSIM (J21.2 SWD.2)
SYS_RESET: 02 - Power, reset (R5.2), 03 - CCIMX93 Power, Control, MCA (U7.AN25), 08 - JTAG, SWD, uSD, Mini PCIe, uSIM (J21.10 SWD.10)
TAMPER0: 04 - CCIMX93 Digital interfaces (U7.G29), 18 - Expansion connectors, LEDs and buttons (J48.6)
TAMPER1: 04 - CCIMX93 Digital interfaces (U7.F29), 18 - Expansion connectors, LEDs and buttons (J48.8)
UART7_RX: 04 - CCIMX93 Digital interfaces (U7.R1), 06 - Shared interfaces lines selection (J62.2)
UART7_TX: 04 - CCIMX93 Digital interfaces (U7.P1), 06 - Shared interfaces lines selection (J61.2)
ULED/BUTTON_1: 04 - CCIMX93 Digital interfaces (U7.E4), 18 - Expansion connectors, LEDs and buttons (D17.K SW4.1 SW4.2)
ULED/BUTTON_2: 06 - Shared interfaces lines selection (J53.3), 18 - Expansion connectors, LEDs and buttons (D18.K SW5.1 SW5.2)
USB_HUB_N: 04 - CCIMX93 Digital interfaces (U7.A8), 13 - USB HUB (U20.30)
USB_HUB_P: 04 - CCIMX93 Digital interfaces (U7.A9), 13 - USB HUB (U20.31)
USB_OTG1_N: 04 - CCIMX93 Digital interfaces (U7.A6), 14 - USB Type C (D16.1 D16.10 J63.A7 J63.B7)
USB_OTG1_P: 04 - CCIMX93 Digital interfaces (U7.A7), 14 - USB Type C (D16.2 D16.9 J63.A6 J63.B6)
USB_PCIe_D_N: 08 - JTAG, SWD, uSD, Mini PCIe, uSIM (J19.36), 13 - USB HUB (L26.3 U25.2)
USB_PCIe_D_P: 08 - JTAG, SWD, uSD, Mini PCIe, uSIM (J19.38), 13 - USB HUB (L26.2 U25.1)
USBC_ALERT_N_3V3: 06 - Shared interfaces lines selection (U33.1), 14 - USB Type C (R51.2 U23.10)
USBC_INT_B_3V3: 06 - Shared interfaces lines selection (U33.8), 14 - USB Type C (U23.9)
USBC_SCL: 14 - USB Type C (U23.8), 17 - I2C, XBee, MIKROBUS (R46.2)
USBC_SDA: 14 - USB Type C (U23.7), 17 - I2C, XBee, MIKROBUS (R47.2)
WL_DEV_WAKE: 05 - CCIMX93 RF (U7.F24), 18 - Expansion connectors, LEDs and buttons (J41.16)
WL_HOST_WAKE: 05 - CCIMX93 RF (U7.G18), 18 - Expansion connectors, LEDs and buttons (J41.18)
WLAN_SD3_CLK: 05 - CCIMX93 RF (R52.2), 18 - Expansion connectors, LEDs and buttons (J41.2)
WLAN_SD3_CMD: 05 - CCIMX93 RF (R53.2), 18 - Expansion connectors, LEDs and buttons (J41.4)
WLAN_SD3_D0: 05 - CCIMX93 RF (R54.2), 18 - Expansion connectors, LEDs and buttons (J41.6)
WLAN_SD3_D1: 05 - CCIMX93 RF (R55.2), 18 - Expansion connectors, LEDs and buttons (J41.8)
WLAN_SD3_D2: 05 - CCIMX93 RF (R56.2), 18 - Expansion connectors, LEDs and buttons (J41.10)
WLAN_SD3_D3: 05 - CCIMX93 RF (R57.2), 18 - Expansion connectors, LEDs and buttons (J41.12)
XBEE_RESET_N: 04 - CCIMX93 Digital interfaces (U7.E3), 17 - I2C, XBee, MIKROBUS (J37.5)
XBEE_UART_CTS_3V3: 06 - Shared interfaces lines selection (U35.1), 17 - I2C, XBee, MIKROBUS (J38.9)
XBEE_UART_RTS_3V3: 06 - Shared interfaces lines selection (U35.8), 17 - I2C, XBee, MIKROBUS (J38.5 R198.2)
XBEE_UART_RX_3V3: 06 - Shared interfaces lines selection (U34.1), 17 - I2C, XBee, MIKROBUS (J37.2)
XBEE_UART_TX_3V3: 06 - Shared interfaces lines selection (U34.8), 17 - I2C, XBee, MIKROBUS (J37.3)
XBEE_USB_D_N: 13 - USB HUB (L27.2 U25.4), 17 - I2C, XBee, MIKROBUS (J37.8)
XBEE_USB_D_P: 13 - USB HUB (L27.3 U25.5), 17 - I2C, XBee, MIKROBUS (J37.7)

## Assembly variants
55002179-01: not fitted C6 C7 C8 C10 C13 C160 C185 C189 C190 C191 D2 J3 J5 J6 J7 J8 J9 J12 J21 J29 J34 J41 J42 J44 J46 J47 J48 J66 L33 L38 L42 Q1 R1 R2 R3 R6 R7 R8 R13 R14 R16 R18 R19 R20 R21 R22 R27 R36 R37 R40 R51 R59 R60 R73 R85 R87 R95 R96 R101 R104 R111 R115 R121 R132 R135 R138 R167 R176 R177 R188 R190 R194 R196 R197 R198 R200 R203 R212 R213 R214 R215 R216 R217 R218 R219 R220 R221 R222 R223 R225 R226 R241 R243 R244 U2 U3 U4 U29; alternate parts R9 -> 1000480, U18 -> 1002785, R119 -> 1000537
